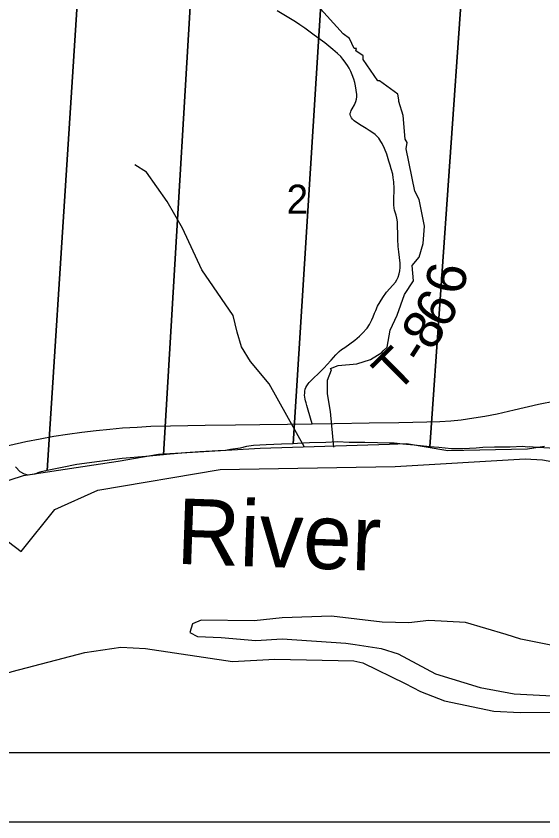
# Model space of a CAD drawing. Extents: x -2.1 to 31.9, y 6.3 to 28.3.
# Drawn here: x 4.384 to 5.147, y 20.344 to 21.508 of the extents above; entities that cross this region are included whole.
import ezdxf

# ---------------------------------------------------------------- set-up
doc = ezdxf.new("R2010")
doc.units = 0
for name, color, linetype in [('Default', 7, 'Continuous'), ('GM_X_Major_River', 7, 'Continuous'), ('GM_X_Major_River_Text', 7, 'Continuous'), ('GM_X_Minor_River', 7, 'Continuous'), ('GM_X_Section', 7, 'Continuous'), ('GM_X_Section_Text', 7, 'Continuous'), ('GM_X_State_Route', 7, 'Continuous'), ('GM_X_Township_Road', 7, 'Continuous'), ('GM_X_Township_Road_Text', 7, 'Continuous'), ('SH_Cut_Line', 7, 'Continuous'), ('SH_Data', 7, 'Continuous')]:
    doc.layers.add(name, color=color, linetype=linetype)

msp = doc.modelspace()

# ---------------------------------------------------------------- linework, layer by layer
at = {"layer": 'Default'}
msp.add_lwpolyline([(4.4901, 23.6442), (4.4651, 23.2405), (4.4383, 22.8067), (4.4168, 22.5238), (4.3751, 21.8979), (4.3091, 20.8714), (4.3023, 20.7658), (4.3525, 20.764), (4.3916, 20.7347), (4.4406, 20.7955), (4.5025, 20.8232), (4.6795, 20.8531), (4.9328, 20.8577), (5.1211, 20.8684), (5.1462, 20.8673), (5.351, 20.8306)], dxfattribs=at)
at = {"layer": 'GM_X_Major_River'}
msp.add_line((4.3946, 20.8439), (4.3197, 20.8204), dxfattribs=at)
for points in [[(5.1242, 20.8828), (5.0091, 20.8803), (4.9493, 20.8905), (4.9248, 20.8893), (4.7376, 20.8834), (4.5904, 20.8749), (4.5322, 20.8646), (4.3946, 20.8439)], [(5.1488, 20.8866), (5.1242, 20.8828)], [(5.1147, 20.6081), (5.0934, 20.6147), (5.0347, 20.632), (4.9814, 20.635), (4.9526, 20.6316), (4.9141, 20.6327), (4.8407, 20.6413), (4.7696, 20.6389), (4.7291, 20.6343), (4.6523, 20.6354), (4.6395, 20.6304), (4.6357, 20.6175), (4.6467, 20.6118), (4.6811, 20.6104), (4.7314, 20.6059), (4.7692, 20.6086), (4.8615, 20.6023), (4.8751, 20.6004), (4.9126, 20.5944), (4.9372, 20.5868), (4.9913, 20.5577), (5.056, 20.5384), (5.1052, 20.529)], [(5.1052, 20.529), (5.2057, 20.5236), (5.2152, 20.5115), (5.228, 20.5153), (5.2409, 20.5252), (5.2489, 20.5377), (5.2591, 20.5468), (5.2724, 20.551), (5.278, 20.5616), (5.2685, 20.5722), (5.2458, 20.5787), (5.2257, 20.5802), (5.1582, 20.5994), (5.1147, 20.6081)], [(4.1054, 20.444), (4.1745, 20.4812), (4.1896, 20.4881), (4.2939, 20.5348), (4.379, 20.5615), (4.4841, 20.5889), (4.5359, 20.5965), (4.5718, 20.5943), (4.6974, 20.5759), (4.7587, 20.579), (4.8729, 20.5765), (4.8861, 20.5738), (4.9474, 20.544), (4.9694, 20.5322), (5.0042, 20.519), (5.0757, 20.5039), (5.1135, 20.5021)], [(5.1135, 20.5021), (5.2019, 20.5027), (5.2375, 20.5054), (5.2493, 20.5096), (5.2595, 20.5146), (5.297, 20.5264), (5.3683, 20.5253), (5.4414, 20.5148), (5.5339, 20.5149), (5.5775, 20.5029), (5.6215, 20.4862), (5.7042, 20.4529), (5.7198, 20.444)]]:
    msp.add_lwpolyline(points, dxfattribs=at)
at = {"layer": 'GM_X_Minor_River'}
for points in [[(4.8442, 20.8857), (4.8393, 20.9369), (4.8348, 20.9627), (4.8351, 20.9821), (4.8408, 20.9973), (4.8393, 20.9992), (4.8506, 21.0034), (4.8775, 21.0061), (4.8971, 21.0123), (4.9137, 21.0222), (4.9156, 21.0245), (4.9213, 21.0302), (4.9258, 21.0545), (4.9356, 21.0762), (4.9462, 21.1059), (4.9594, 21.126), (4.9575, 21.1481), (4.9677, 21.1599), (4.9733, 21.18), (4.9752, 21.2047), (4.9676, 21.2435), (4.9615, 21.2553), (4.9486, 21.3164), (4.9501, 21.3259), (4.9471, 21.3308), (4.9444, 21.365), (4.938, 21.3848), (4.938, 21.3874), (4.9365, 21.3958), (4.9104, 21.4151), (4.9077, 21.4151), (4.8865, 21.4459), (4.8865, 21.4508), (4.8759, 21.458), (4.8767, 21.4618), (4.8736, 21.4614), (4.8668, 21.4762), (4.8574, 21.483), (4.8207, 21.5236)], [(4.8018, 20.8857), (4.7505, 20.9768), (4.7235, 21.0094), (4.7106, 21.0303), (4.7041, 21.0515), (4.6987, 21.0758), (4.6534, 21.1415), (4.6252, 21.2019), (4.6031, 21.2406), (4.5731, 21.2827), (4.5563, 21.2937)]]:
    msp.add_lwpolyline(points, dxfattribs=at)
at = {"layer": 'GM_X_Section'}
msp.add_lwpolyline([(4.4881, 21.7655), (4.4292, 20.8518), (4.4187, 20.8494), (4.4157, 20.8483), (4.4116, 20.8464), (4.4081, 20.846), (4.4021, 20.8452), (4.3964, 20.8464), (4.3903, 20.8498), (4.3835, 20.8569)], dxfattribs=at)
for points in [[(4.4881, 21.7655), (4.6504, 21.7575), (4.5978, 20.8744), (4.5722, 20.8721), (4.5381, 20.869), (4.4721, 20.8602), (4.4513, 20.8563), (4.4415, 20.854), (4.4292, 20.8518)], [(4.6504, 21.7575), (4.8395, 21.7479), (4.7851, 20.8904), (4.7684, 20.8896), (4.746, 20.8888), (4.7278, 20.888), (4.718, 20.8865), (4.7085, 20.8838), (4.6945, 20.8819), (4.6873, 20.8807), (4.6767, 20.8803), (4.6502, 20.8787), (4.6294, 20.8772), (4.6021, 20.8748), (4.5978, 20.8744)], [(4.8395, 21.7479), (5.043, 21.7379), (4.9832, 20.8861), (4.9605, 20.8885), (4.9438, 20.89), (4.9313, 20.8911), (4.9245, 20.8911), (4.9071, 20.8918), (4.8892, 20.8921), (4.8665, 20.8924), (4.8495, 20.8932), (4.8328, 20.8924), (4.8089, 20.8916), (4.7915, 20.8908), (4.7851, 20.8904)], [(5.043, 21.7379), (5.2409, 21.7347), (5.1841, 20.8829), (5.1718, 20.8832), (5.1324, 20.8853), (5.1275, 20.8861), (5.1249, 20.8854), (5.117, 20.8862), (5.0992, 20.8854), (5.0844, 20.8853), (5.0764, 20.8857), (5.0598, 20.8849), (5.0499, 20.8841), (5.031, 20.8833), (5.0143, 20.8829), (4.9961, 20.8848), (4.9832, 20.8861)]]:
    msp.add_lwpolyline(points, close=True, dxfattribs=at)
at = {"layer": 'GM_X_State_Route'}
for points in [[(4.8129, 20.9194), (4.8445, 20.9198), (4.8953, 20.9206), (4.938, 20.9212), (4.9789, 20.922), (4.9975, 20.9227), (5.0136, 20.9237), (5.0284, 20.9252), (5.0377, 20.9264), (5.0468, 20.9277), (5.0627, 20.9303), (5.0803, 20.9338), (5.1051, 20.9393), (5.1402, 20.9475), (5.1646, 20.9526)], [(4.3093, 20.8708), (4.3251, 20.8755), (4.3515, 20.8826), (4.3755, 20.8884), (4.3984, 20.8935), (4.4194, 20.8977), (4.439, 20.9013), (4.459, 20.9044), (4.4797, 20.9072), (4.5005, 20.9097), (4.52, 20.9116), (4.5386, 20.9132), (4.5594, 20.9146), (4.5794, 20.9156), (4.6076, 20.9163), (4.6581, 20.9172), (4.7018, 20.9178), (4.7372, 20.9183), (4.7769, 20.9189), (4.8129, 20.9194)]]:
    msp.add_lwpolyline(points, dxfattribs=at)
at = {"layer": 'GM_X_Township_Road'}
for points in [[(4.891, 21.0562), (4.8922, 21.0576), (4.8957, 21.0628), (4.8992, 21.0696), (4.9009, 21.0736), (4.9029, 21.0791), (4.9047, 21.083), (4.9075, 21.0891), (4.911, 21.0956), (4.9151, 21.1017), (4.9203, 21.1093), (4.9297, 21.1194), (4.9333, 21.1238), (4.9355, 21.1274), (4.9371, 21.131), (4.9388, 21.1358), (4.9397, 21.1405), (4.9402, 21.1453), (4.94, 21.1512), (4.9381, 21.1676), (4.9373, 21.1753), (4.937, 21.1789), (4.9368, 21.1826), (4.9367, 21.1876), (4.9361, 21.2109), (4.9354, 21.2163), (4.9344, 21.2205), (4.9327, 21.2253), (4.9319, 21.2282), (4.9314, 21.2308), (4.9311, 21.2356), (4.9308, 21.2421), (4.9313, 21.2594), (4.9309, 21.2688), (4.9302, 21.2746), (4.9293, 21.2801), (4.9272, 21.2878), (4.9258, 21.2932), (4.9239, 21.299), (4.9206, 21.3091), (4.9175, 21.3171), (4.9139, 21.3241), (4.912, 21.3274), (4.9106, 21.3296), (4.909, 21.3318), (4.9073, 21.3337), (4.9039, 21.3374), (4.9005, 21.3398), (4.8954, 21.3431), (4.8908, 21.3459), (4.8836, 21.3504), (4.8783, 21.3537), (4.8735, 21.3572), (4.8712, 21.3593), (4.8697, 21.3614), (4.8683, 21.3643), (4.8678, 21.3663), (4.868, 21.3682), (4.8686, 21.3699), (4.8693, 21.3719), (4.8708, 21.3744), (4.8738, 21.3801), (4.8761, 21.3851), (4.8769, 21.3882), (4.8774, 21.3916), (4.8773, 21.3951), (4.8766, 21.4015), (4.8755, 21.4075), (4.8744, 21.4124), (4.873, 21.4172), (4.8708, 21.4235), (4.8687, 21.4282), (4.8663, 21.433), (4.8639, 21.4369), (4.8591, 21.4437), (4.8572, 21.4462), (4.8545, 21.4498), (4.8494, 21.4544), (4.8426, 21.4602), (4.8309, 21.4696), (4.8158, 21.4811), (4.8023, 21.4909), (4.7951, 21.4958), (4.7899, 21.4991), (4.7863, 21.5014), (4.779, 21.5061), (4.7623, 21.5161)], [(4.8396, 21.0107), (4.8403, 21.0114), (4.8468, 21.0187), (4.8519, 21.0237), (4.8553, 21.0267), (4.86, 21.0297), (4.8671, 21.0346), (4.8747, 21.0402), (4.8812, 21.0459), (4.8868, 21.0513), (4.891, 21.0562)], [(4.8129, 20.9194), (4.8105, 20.9272), (4.8061, 20.9421), (4.805, 20.9457), (4.8041, 20.9493), (4.8033, 20.9522), (4.8027, 20.9548), (4.8022, 20.9576), (4.8019, 20.9608), (4.802, 20.9633), (4.8022, 20.9665), (4.8029, 20.9693), (4.8038, 20.9715), (4.8051, 20.974), (4.8071, 20.9771), (4.8085, 20.9788), (4.8107, 20.9813), (4.8132, 20.9838), (4.8236, 20.9936), (4.8302, 21.0002), (4.8345, 21.0051), (4.8396, 21.0107)]]:
    msp.add_lwpolyline(points, dxfattribs=at)
at = {"layer": 'SH_Cut_Line'}
msp.add_lwpolyline([(0.0344, 20.444), (3.7533, 20.444), (3.8489, 20.5389), (3.9894, 20.6326), (4.16, 20.7203), (4.2895, 20.7662), (4.3023, 20.7658), (4.3525, 20.764), (4.3916, 20.7347), (4.4406, 20.7955), (4.5025, 20.8232), (4.6795, 20.8531), (4.9328, 20.8577), (5.1211, 20.8684), (5.1462, 20.8673), (5.351, 20.8306)], dxfattribs=at)
at = {"layer": 'SH_Data'}
for p, q in [((0.0344, 20.444), (6.8344, 20.444)), ((-0.0656, 20.344), (6.9344, 20.344))]:
    msp.add_line(p, q, dxfattribs=at)

# ---------------------------------------------------------------- texts
at = {"layer": 'GM_X_Major_River_Text'}
msp.add_text('River', height=0.0947, rotation=357.9954, dxfattribs=at).set_placement((4.6155, 20.717))
at = {"layer": 'GM_X_Section_Text'}
msp.add_text('2', height=0.0419, rotation=0, dxfattribs=at).set_placement((4.7758, 21.2229))
at = {"layer": 'GM_X_Township_Road_Text'}
for s, rotation, p in [('6', 79.4082, (5.031, 21.104)), ('6', 59.6752, (5.006, 21.0539)), ('8', 58.1295, (4.9866, 21.0227)), ('T', 44.6773, (4.9348, 20.9618)), ('-', 57.3982, (4.9736, 21.0024))]:
    msp.add_text(s, height=0.0568, rotation=rotation, dxfattribs=at).set_placement(p)

doc.saveas('drawing.dxf')
